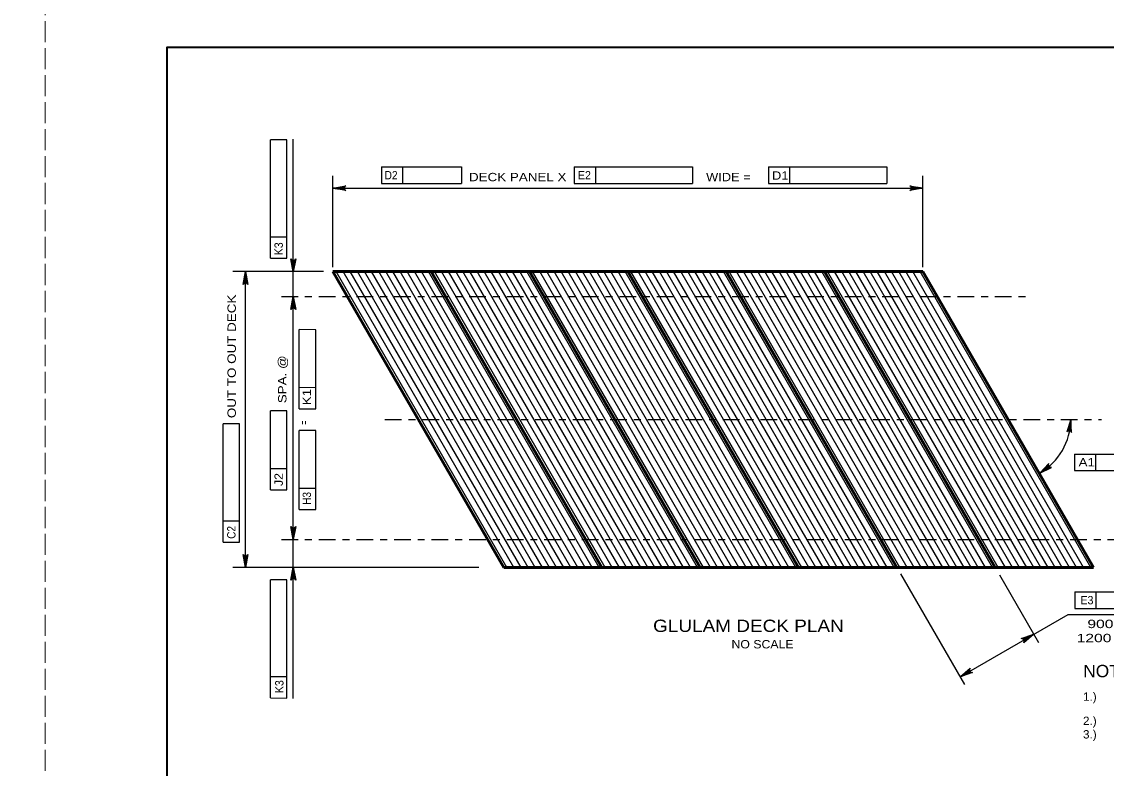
# Model space of a CAD drawing. Extents: x -11 to 79, y -154 to 0.
# Drawn here: x 33.66 to 49.26, y -121.11 to -110.38 of the extents above; entities that cross this region are included whole.
import ezdxf
from ezdxf.enums import TextEntityAlignment as Align

# ---------------------------------------------------------------- set-up
doc = ezdxf.new("R2010")
doc.units = 0
doc.header["$LTSCALE"] = 0.048
doc.linetypes.add('DOT_DASHED', pattern=[7.7, 5, -1.2, 0.3, -1.2])
doc.linetypes.add('LONG_DASHED', pattern=[7.5, 6, -1.5])
for name, color, linetype, lineweight in [('1', 7, 'Continuous', 25), ('2', 7, 'Continuous', 35), ('4', 7, 'Continuous', 25), ('5', 7, 'Continuous', 25), ('63', 7, 'LONG_DASHED', 13)]:
    doc.layers.add(name, color=color, linetype=linetype, lineweight=lineweight)

msp = doc.modelspace()

# ---------------------------------------------------------------- linework, layer by layer
at = {"layer": '1', "lineweight": 35}
msp.add_lwpolyline([(35.75, -131.25), (67.25, -131.25), (67.25, -110.75), (35.75, -110.75)], close=True, dxfattribs=at)
at = {"layer": '2', "lineweight": 53}
for p, q in [((46.61567, -113.97383), (38.13692, -113.97383)), ((40.59175, -118.22583), (38.13692, -113.97383)), ((42.00492, -118.22583), (39.55, -113.97383)), ((43.418, -118.22583), (40.96317, -113.97383)), ((44.83117, -118.22583), (42.37625, -113.97383)), ((46.24425, -118.22583), (43.78942, -113.97383)), ((47.65742, -118.22583), (45.2025, -113.97383)), ((49.0705, -118.22583), (46.61567, -113.97383)), ((40.59175, -118.22583), (49.0705, -118.22583))]:
    msp.add_line(p, q, dxfattribs=at)
at = {"layer": '4'}
for p, q in [((37.47433, -112.07983), (37.23808, -112.07958)), ((37.23808, -113.47792), (37.23808, -112.07958)), ((37.47433, -113.78067), (37.47433, -112.07983)), ((37.56642, -120.10908), (37.56642, -112.07025)), ((38.83642, -112.46975), (39.13883, -112.46975)), ((38.83642, -112.46975), (38.83642, -112.706)), ((39.13883, -112.46975), (39.13883, -112.706)), ((39.13883, -112.46975), (39.983, -112.46975)), ((39.983, -112.46975), (39.983, -112.706)), ((41.60725, -112.46975), (41.90967, -112.46975)), ((41.60725, -112.46975), (41.60725, -112.706)), ((41.90967, -112.46975), (41.90967, -112.706)), ((41.90967, -112.46975), (43.308, -112.46975)), ((43.308, -112.46975), (43.308, -112.706)), ((44.39858, -112.46975), (44.39858, -112.706)), ((44.39858, -112.46975), (44.70108, -112.46975)), ((44.70108, -112.46975), (44.70108, -112.706)), ((44.70108, -112.46975), (46.09942, -112.46975)), ((46.09942, -112.46975), (46.09942, -112.706)), ((38.13692, -113.91133), (38.13692, -112.59475)), ((38.83642, -112.706), (39.983, -112.706)), ((41.60725, -112.706), (43.308, -112.706)), ((44.39858, -112.706), (46.09942, -112.706)), ((46.61567, -113.91133), (46.61567, -112.59475)), ((38.13692, -112.77475), (46.61567, -112.77475)), ((37.23808, -113.78042), (37.23808, -113.47792)), ((37.47433, -113.47817), (37.23808, -113.47792)), ((37.23808, -113.78042), (37.47433, -113.78067)), ((37.99992, -113.97383), (36.6995, -113.97383)), ((36.8795, -118.22583), (36.8795, -113.97383)), ((37.88867, -114.80875), (37.6525, -114.8085)), ((37.6525, -115.64875), (37.6525, -114.8085)), ((37.88867, -115.94492), (37.88867, -114.80875)), ((37.88867, -115.6425), (37.6525, -115.64225)), ((37.6525, -115.94467), (37.6525, -115.64875)), ((37.47433, -115.97558), (37.23808, -115.97533)), ((37.23808, -116.80908), (37.23808, -115.97533)), ((37.47433, -117.11175), (37.47433, -115.97558)), ((37.6525, -115.94467), (37.88867, -115.94492)), ((36.79375, -116.16275), (36.5575, -116.1625)), ((36.5575, -117.56083), (36.5575, -116.1625)), ((36.79375, -117.8635), (36.79375, -116.16275)), ((37.88867, -116.25783), (37.6525, -116.25758)), ((37.6525, -117.09133), (37.6525, -116.25758)), ((37.88867, -117.39408), (37.88867, -116.25783)), ((48.79867, -116.59617), (48.79867, -116.83233)), ((49.10108, -116.59617), (50.49942, -116.59617)), ((37.23808, -117.1115), (37.23808, -116.80908)), ((37.47433, -116.80933), (37.23808, -116.80908)), ((48.79867, -116.83233), (50.49942, -116.83233)), ((37.6525, -117.39383), (37.6525, -117.09133)), ((37.88867, -117.09158), (37.6525, -117.09133)), ((37.23808, -117.1115), (37.47433, -117.11175)), ((37.6525, -117.39383), (37.88867, -117.39408)), ((36.5575, -117.86325), (36.5575, -117.56083)), ((36.79375, -117.56108), (36.5575, -117.56083)), ((36.5575, -117.86325), (36.79375, -117.8635)), ((40.23408, -118.22583), (36.6995, -118.22583)), ((46.2975, -118.31808), (47.21608, -119.908)), ((47.71983, -118.33383), (48.28067, -119.30458)), ((37.47433, -118.40333), (37.23808, -118.40308)), ((37.23808, -119.80142), (37.23808, -118.40308)), ((37.47433, -120.10417), (37.47433, -118.40333)), ((48.80117, -118.579), (48.80117, -118.81517)), ((49.10358, -118.579), (50.50192, -118.579)), ((48.80117, -118.81517), (50.50192, -118.81517)), ((47.15342, -119.7995), (48.70792, -118.9015)), ((48.70792, -118.9015), (50.92625, -118.9015)), ((37.23808, -120.10383), (37.23808, -119.80142)), ((37.47433, -119.80167), (37.23808, -119.80142)), ((37.23808, -120.10383), (37.47433, -120.10417))]:
    msp.add_line(p, q, dxfattribs=at)
at = {"layer": '4', "linetype": 'DOT_DASHED'}
for p, q in [((37.395, -114.3325), (48.19083, -114.3325)), ((38.88392, -116.09983), (49.18825, -116.09983)), ((37.395, -117.8235), (50.09508, -117.8235))]:
    msp.add_line(p, q, dxfattribs=at)
at = {"layer": '4'}
for points in [[(38.13692, -112.77475), (38.32333, -112.73983), (38.309, -112.74975), (38.30158, -112.76225), (38.29942, -112.77475), (38.30158, -112.78725), (38.309, -112.79975), (38.32333, -112.80967), (38.13692, -112.77475), (38.309, -112.79975), (38.30158, -112.78725), (38.13692, -112.77475), (38.29942, -112.77475), (38.30158, -112.76225), (38.13692, -112.77475), (38.309, -112.74975)], [(46.61567, -112.77475), (46.42925, -112.80967), (46.44358, -112.79975), (46.451, -112.78725), (46.45317, -112.77475), (46.451, -112.76225), (46.44358, -112.74975), (46.42925, -112.73983), (46.61567, -112.77475), (46.44358, -112.74975), (46.451, -112.76225), (46.61567, -112.77475), (46.45317, -112.77475), (46.451, -112.78725), (46.61567, -112.77475), (46.44358, -112.79975)], [(37.56642, -113.97858), (37.5315, -113.79217), (37.54142, -113.8065), (37.55392, -113.81392), (37.56642, -113.81608), (37.57892, -113.81392), (37.59142, -113.8065), (37.60133, -113.79217), (37.56642, -113.97858), (37.59142, -113.8065), (37.57892, -113.81392), (37.56642, -113.97858), (37.56642, -113.81608), (37.55392, -113.81392), (37.56642, -113.97858), (37.54142, -113.8065)], [(36.8795, -113.97383), (36.91442, -114.16025), (36.9045, -114.14592), (36.892, -114.1385), (36.8795, -114.13633), (36.867, -114.1385), (36.8545, -114.14592), (36.84458, -114.16025), (36.8795, -113.97383), (36.8545, -114.14592), (36.867, -114.1385), (36.8795, -113.97383), (36.8795, -114.13633), (36.892, -114.1385), (36.8795, -113.97383), (36.9045, -114.14592)], [(37.56642, -114.3325), (37.60133, -114.51883), (37.59142, -114.5045), (37.57892, -114.49708), (37.56642, -114.495), (37.55392, -114.49708), (37.54142, -114.5045), (37.5315, -114.51883), (37.56642, -114.3325), (37.54142, -114.5045), (37.55392, -114.49708), (37.56642, -114.3325), (37.56642, -114.495), (37.57892, -114.49708), (37.56642, -114.3325), (37.59142, -114.5045)], [(48.74367, -116.09892), (48.68583, -116.2795), (48.69742, -116.2665), (48.71075, -116.26075), (48.72342, -116.26017), (48.73558, -116.26383), (48.74708, -116.27275), (48.75517, -116.28825), (48.74367, -116.09892), (48.74708, -116.27275), (48.73558, -116.26383), (48.74367, -116.09892), (48.72342, -116.26017), (48.71075, -116.26075), (48.74367, -116.09892), (48.69742, -116.2665)], [(48.79867, -116.59617), (49.10108, -116.59617), (49.10108, -116.83233)], [(48.2985, -116.87217), (48.46967, -116.79058), (48.45217, -116.79092), (48.43883, -116.78525), (48.42967, -116.77642), (48.42408, -116.765), (48.42275, -116.75058), (48.42842, -116.73408), (48.2985, -116.87217), (48.42275, -116.75058), (48.42408, -116.765), (48.2985, -116.87217), (48.42967, -116.77642), (48.43883, -116.78525), (48.2985, -116.87217), (48.45217, -116.79092)], [(37.56642, -117.8235), (37.5315, -117.63708), (37.54142, -117.65142), (37.55392, -117.65883), (37.56642, -117.661), (37.57892, -117.65883), (37.59142, -117.65142), (37.60133, -117.63708), (37.56642, -117.8235), (37.59142, -117.65142), (37.57892, -117.65883), (37.56642, -117.8235), (37.56642, -117.661), (37.55392, -117.65883), (37.56642, -117.8235), (37.54142, -117.65142)], [(36.8795, -118.22583), (36.84458, -118.03942), (36.8545, -118.05375), (36.867, -118.06117), (36.8795, -118.06333), (36.892, -118.06117), (36.9045, -118.05375), (36.91442, -118.03942), (36.8795, -118.22583), (36.9045, -118.05375), (36.892, -118.06117), (36.8795, -118.22583), (36.8795, -118.06333), (36.867, -118.06117), (36.8795, -118.22583), (36.8545, -118.05375)], [(37.56642, -118.22133), (37.60133, -118.40775), (37.59142, -118.39342), (37.57892, -118.386), (37.56642, -118.38383), (37.55392, -118.386), (37.54142, -118.39342), (37.5315, -118.40775), (37.56642, -118.22133), (37.54142, -118.39342), (37.55392, -118.386), (37.56642, -118.22133), (37.56642, -118.38383), (37.57892, -118.386), (37.56642, -118.22133), (37.59142, -118.39342)], [(48.80117, -118.579), (49.10358, -118.579), (49.10358, -118.81517)], [(48.21292, -119.18742), (48.069, -119.31092), (48.07642, -119.29517), (48.07658, -119.28058), (48.07225, -119.26867), (48.06408, -119.25892), (48.05142, -119.25183), (48.034, -119.25042), (48.21292, -119.18742), (48.05142, -119.25183), (48.06408, -119.25892), (48.21292, -119.18742), (48.07225, -119.26867), (48.07658, -119.28058), (48.21292, -119.18742), (48.07642, -119.29517)], [(47.15342, -119.7995), (47.29733, -119.676), (47.28992, -119.69175), (47.28975, -119.70633), (47.29408, -119.71825), (47.30225, -119.728), (47.31492, -119.73508), (47.33233, -119.7365), (47.15342, -119.7995), (47.31492, -119.73508), (47.30225, -119.728), (47.15342, -119.7995), (47.29408, -119.71825), (47.28975, -119.70633), (47.15342, -119.7995), (47.28992, -119.69175)]]:
    msp.add_lwpolyline(points, dxfattribs=at)
msp.add_arc((47.85248, -116.09984), 0.89111, 299.99935, 0.00063, dxfattribs=at)
at = {"layer": '5'}
for p, q in [((40.63683, -118.22583), (38.182, -113.97383)), ((40.73917, -118.22583), (38.28425, -113.97383)), ((40.84142, -118.22583), (38.38658, -113.97383)), ((40.94375, -118.22583), (38.48883, -113.97383)), ((41.046, -118.22583), (38.59117, -113.97383)), ((41.14825, -118.22583), (38.69342, -113.97383)), ((41.25058, -118.22583), (38.79567, -113.97383)), ((41.35283, -118.22583), (38.898, -113.97383)), ((41.45517, -118.22583), (39.00025, -113.97383)), ((41.55742, -118.22583), (39.10258, -113.97383)), ((41.65975, -118.22583), (39.20483, -113.97383)), ((41.762, -118.22583), (39.30717, -113.97383)), ((41.86425, -118.22583), (39.40942, -113.97383)), ((41.96658, -118.22583), (39.51175, -113.97383)), ((42.05, -118.22583), (39.59508, -113.97383)), ((42.15225, -118.22583), (39.69742, -113.97383)), ((42.25458, -118.22583), (39.79967, -113.97383)), ((42.35683, -118.22583), (39.902, -113.97383)), ((42.45917, -118.22583), (40.00425, -113.97383)), ((42.56142, -118.22583), (40.10658, -113.97383)), ((42.66367, -118.22583), (40.20883, -113.97383)), ((42.766, -118.22583), (40.31108, -113.97383)), ((42.86825, -118.22583), (40.41342, -113.97383)), ((42.97058, -118.22583), (40.51567, -113.97383)), ((43.07283, -118.22583), (40.618, -113.97383)), ((43.17517, -118.22583), (40.72025, -113.97383)), ((43.27742, -118.22583), (40.82258, -113.97383)), ((43.37967, -118.22583), (40.92483, -113.97383)), ((43.46308, -118.22583), (41.00825, -113.97383)), ((43.56542, -118.22583), (41.1105, -113.97383)), ((43.66767, -118.22583), (41.21283, -113.97383)), ((43.77, -118.22583), (41.31508, -113.97383)), ((43.87225, -118.22583), (41.41742, -113.97383)), ((43.9745, -118.22583), (41.51967, -113.97383)), ((44.07683, -118.22583), (41.62192, -113.97383)), ((44.17908, -118.22583), (41.72425, -113.97383)), ((44.28142, -118.22583), (41.8265, -113.97383)), ((44.38367, -118.22583), (41.92883, -113.97383)), ((44.486, -118.22583), (42.03108, -113.97383)), ((44.58825, -118.22583), (42.13342, -113.97383)), ((44.69058, -118.22583), (42.23567, -113.97383)), ((44.79283, -118.22583), (42.338, -113.97383)), ((44.87625, -118.22583), (42.42133, -113.97383)), ((44.9785, -118.22583), (42.52367, -113.97383)), ((45.08083, -118.22583), (42.62592, -113.97383)), ((45.18308, -118.22583), (42.72825, -113.97383)), ((45.28542, -118.22583), (42.8305, -113.97383)), ((45.38767, -118.22583), (42.93283, -113.97383)), ((45.48992, -118.22583), (43.03508, -113.97383)), ((45.59225, -118.22583), (43.13733, -113.97383)), ((45.6945, -118.22583), (43.23967, -113.97383)), ((45.79683, -118.22583), (43.34192, -113.97383)), ((45.89908, -118.22583), (43.44425, -113.97383)), ((46.00142, -118.22583), (43.5465, -113.97383)), ((46.10367, -118.22583), (43.64883, -113.97383)), ((46.20592, -118.22583), (43.75108, -113.97383)), ((46.28933, -118.22583), (43.8345, -113.97383)), ((46.39167, -118.22583), (43.93675, -113.97383)), ((46.49392, -118.22583), (44.03908, -113.97383)), ((46.59625, -118.22583), (44.14133, -113.97383)), ((46.6985, -118.22583), (44.24367, -113.97383)), ((46.80075, -118.22583), (44.34592, -113.97383)), ((46.90308, -118.22583), (44.44817, -113.97383)), ((47.00533, -118.22583), (44.5505, -113.97383)), ((47.10767, -118.22583), (44.65275, -113.97383)), ((47.20992, -118.22583), (44.75508, -113.97383)), ((47.31225, -118.22583), (44.85733, -113.97383)), ((47.4145, -118.22583), (44.95967, -113.97383)), ((47.51683, -118.22583), (45.06192, -113.97383)), ((47.61908, -118.22583), (45.16425, -113.97383)), ((47.7025, -118.22583), (45.24758, -113.97383)), ((47.80475, -118.22583), (45.34992, -113.97383)), ((47.90708, -118.22583), (45.45217, -113.97383)), ((48.00933, -118.22583), (45.5545, -113.97383)), ((48.11167, -118.22583), (45.65675, -113.97383)), ((48.21392, -118.22583), (45.75908, -113.97383)), ((48.31617, -118.22583), (45.86133, -113.97383)), ((48.4185, -118.22583), (45.96358, -113.97383)), ((48.52075, -118.22583), (46.06592, -113.97383)), ((48.62308, -118.22583), (46.16817, -113.97383)), ((48.72533, -118.22583), (46.2705, -113.97383)), ((48.82767, -118.22583), (46.37275, -113.97383)), ((48.92992, -118.22583), (46.47508, -113.97383)), ((49.03217, -118.22583), (46.57733, -113.97383))]:
    msp.add_line(p, q, dxfattribs=at)
at = {"layer": '63'}
for points in [[(0, -132), (34, -132), (34, -110), (0, -110)], [(34, -132), (68, -132), (68, -110), (34, -110)]]:
    msp.add_lwpolyline(points, close=True, dxfattribs=at)

# ---------------------------------------------------------------- texts
at = {"layer": '4'}
for s, rotation, width, p in [('D2', 359.938, 0.9, (38.97277, -112.64793)), ('E2', 359.938, 0.95, (41.75185, -112.64793)), ('D1', 359.938, 1.15, (44.56735, -112.65246)), ('K3', 89.938, 0.95, (37.41618, -113.64648)), ('OUT TO OUT DECK', 90, 1.2, (36.74083, -115.19308)), ('K1', 89.938, 1.2, (37.82096, -115.77756)), ('A1', 359.938, 1.2, (48.97485, -116.7743)), ('J2', 89.938, 1.1, (37.41627, -116.96273)), ('H3', 89.938, 0.9, (37.82093, -117.2349)), ('C2', 89.938, 0.9, (36.73568, -117.72306)), ('E3', 359.938, 0.95, (48.97735, -118.7571)), ('K3', 89.938, 0.95, (37.42577, -119.94098))]:
    msp.add_text(s, height=0.12, rotation=rotation, dxfattribs=dict(at, width=width)).set_placement(p, align=Align.CENTER)
for s, height, width, p in [('DECK PANEL X', 0.12, 1.2, (40.09217, -112.67475)), ('WIDE =', 0.12, 1.15, (43.50233, -112.67475)), ('NO SCALE', 0.12, 1.1, (43.86683, -119.39083)), ('NOTES:', 0.1772, 1.05, (48.924, -119.80483)), ('1.)', 0.12, 1.05, (48.92058, -120.14408)), ('2.)', 0.12, 1.05, (48.92058, -120.49217)), ('3.)', 0.12, 1.05, (48.92058, -120.68608))]:
    msp.add_text(s, height=height, dxfattribs=dict(at, width=width)).set_placement(p)
for s, width, p in [('SPA. @', 1.2, (37.46833, -115.86592)), ('=', 0.6, (37.77742, -116.17658))]:
    msp.add_text(s, height=0.12, rotation=90, dxfattribs=dict(at, width=width)).set_placement(p)
for s, height, width, p in [('GLULAM DECK PLAN', 0.1772, 1.15, (44.11025, -119.15467)), ('900 (3\'-0")MIN.', 0.12, 1.4, (49.73775, -119.09883)), ('1200 (4\'-0")MAX.', 0.12, 1.4, (49.68379, -119.30158))]:
    msp.add_text(s, height=height, dxfattribs=dict(at, width=width)).set_placement(p, align=Align.CENTER)

doc.saveas('drawing.dxf')
